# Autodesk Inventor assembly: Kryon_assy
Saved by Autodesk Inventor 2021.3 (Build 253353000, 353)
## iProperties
Created: 2021-10
Part Number: Kryon_assy
Document SubType Name: Assembly
Designer: Administrator
Title: Kryon_assy v16
Author: Administrator
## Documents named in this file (5)
- c:\worker\convert-fusion-r07\tmp\job-1\104\output\files\1b52018f-34f2-46a2-838f-1ebc97158f15\cd9648ca-4348-4626-bfab-f9cd8a06a14d.iam
- c:\worker\convert-fusion-r07\tmp\job-1\104\output\files\1b52018f-34f2-46a2-838f-1ebc97158f15\rotating v7.ipt
- c:\worker\convert-fusion-r07\tmp\job-1\104\output\files\1b52018f-34f2-46a2-838f-1ebc97158f15\magnet v3.ipt
- c:\worker\convert-fusion-r07\tmp\job-1\104\output\files\1b52018f-34f2-46a2-838f-1ebc97158f15\stator v7.ipt
- c:\worker\convert-fusion-r07\tmp\job-1\104\output\files\1b52018f-34f2-46a2-838f-1ebc97158f15\Stator-center v3.ipt
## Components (15 placed, 4 different names)
1. rotating v7:1
2. magnet v3:1
3. magnet v3:2
4. magnet v3:3
5. magnet v3:4
6. stator v7:1
7. Stator-center v3:1
8. magnet v3:5
9. magnet v3:6
10. magnet v3:7
11. magnet v3:8
12. magnet v3:9
13. magnet v3:10
14. magnet v3:11
15. magnet v3:12
